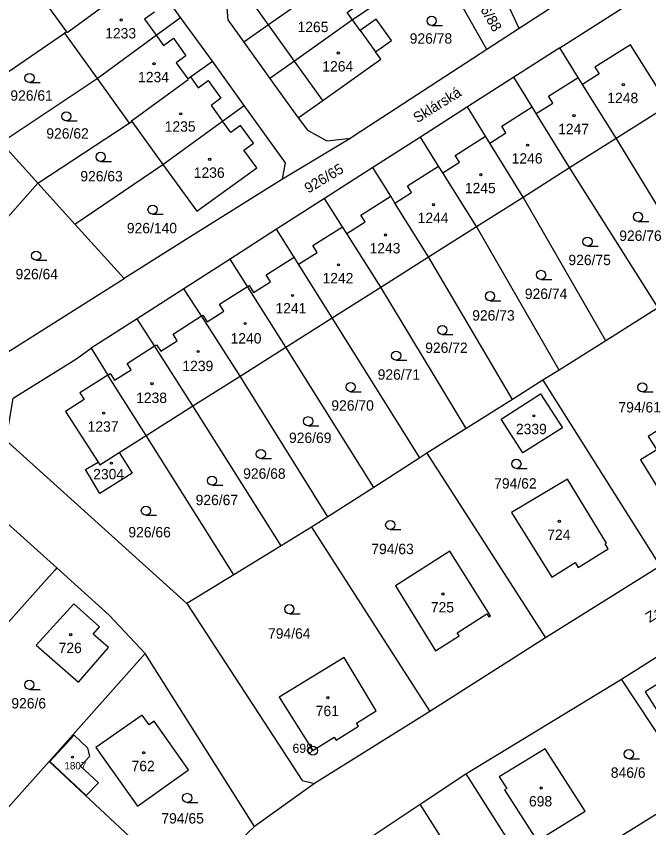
# Model space of a CAD drawing. Extents: x -680203 to -673936, y -1102717 to -1093650.
# Drawn here: x -679209.6 to -679106, y -1097911.3 to -1097778.4 of the extents above; entities that cross this region are included whole.
import ezdxf

# ---------------------------------------------------------------- set-up
doc = ezdxf.new("R2010")
doc.units = 0
for name, color, linetype in [('SOxx02xx_Koleje_param další_Popis10', 7, 'Continuous'), ('SOxx02xx_Staničení_Popis10', 7, 'Continuous'), ('SOxxxxxx_Koleje_hlavní_body_Popis10', 7, 'Continuous'), ('SOxxxxxx_Koleje_param další_Popis10', 7, 'Continuous'), ('SOxxxxxx_Osa_bod_P', 7, 'Continuous'), ('SOxxxxxx_Staničení_Popis10', 7, 'Continuous'), ('x_prac', 7, 'Continuous')]:
    doc.layers.add(name, color=color, linetype=linetype)

msp = doc.modelspace()

# ---------------------------------------------------------------- linework, layer by layer
at = {"layer": 'SOxx02xx_Koleje_param další_Popis10'}
for radius in [0.75, 0.03]:
    msp.add_circle((-679160.97, -1097898.67), radius, dxfattribs=at)
at = {"layer": 'SOxxxxxx_Koleje_hlavní_body_Popis10'}
for p, q in [((-679141.5, -1097779.94), (-679139.75, -1097779.94)), ((-679207.39, -1097789.29), (-679205.64, -1097789.29)), ((-679201.35, -1097795.58), (-679199.6, -1097795.58)), ((-679195.73, -1097802.2), (-679193.98, -1097802.2)), ((-679187.23, -1097810.84), (-679185.48, -1097810.84)), ((-679107.71, -1097812.03), (-679105.96, -1097812.03)), ((-679115.99, -1097816.08), (-679114.24, -1097816.08)), ((-679206.29, -1097818.38), (-679204.54, -1097818.38)), ((-679123.59, -1097821.53), (-679121.84, -1097821.53)), ((-679131.95, -1097825.02), (-679130.2, -1097825.02)), ((-679139.77, -1097830.56), (-679138.02, -1097830.56)), ((-679147.33, -1097834.75), (-679145.58, -1097834.75)), ((-679154.79, -1097839.9), (-679153.04, -1097839.9)), ((-679107, -1097839.95), (-679105.25, -1097839.95)), ((-679161.75, -1097845.49), (-679160, -1097845.49)), ((-679169.5, -1097850.86), (-679167.75, -1097850.86)), ((-679127.63, -1097852.47), (-679125.88, -1097852.47)), ((-679177.48, -1097855.22), (-679175.73, -1097855.22)), ((-679188.32, -1097860.13), (-679186.57, -1097860.13)), ((-679148.3, -1097862.48), (-679146.55, -1097862.48)), ((-679164.82, -1097876.26), (-679163.07, -1097876.26)), ((-679207.41, -1097888.64), (-679205.66, -1097888.64)), ((-679109.22, -1097900), (-679107.47, -1097900)), ((-679181.56, -1097907.16), (-679179.81, -1097907.16))]:
    msp.add_line(p, q, dxfattribs=at)
for centre in [(-679141.5, -1097779.19), (-679207.39, -1097788.54), (-679201.35, -1097794.83), (-679195.73, -1097801.45), (-679187.23, -1097810.09), (-679107.71, -1097811.28), (-679115.99, -1097815.33), (-679206.29, -1097817.63), (-679123.59, -1097820.78), (-679131.95, -1097824.27), (-679139.77, -1097829.81), (-679147.33, -1097834), (-679154.79, -1097839.15), (-679107, -1097839.2), (-679161.75, -1097844.74), (-679169.5, -1097850.11), (-679127.63, -1097851.72), (-679177.48, -1097854.47), (-679188.32, -1097859.38), (-679148.3, -1097861.73), (-679164.82, -1097875.51), (-679207.41, -1097887.89), (-679109.22, -1097899.25), (-679181.56, -1097906.41)]:
    msp.add_circle(centre, 0.75, dxfattribs=at)
at = {"layer": 'SOxxxxxx_Koleje_param další_Popis10'}
for centre in [(-679192.37, -1097779.05), (-679156.81, -1097784.45), (-679186.99, -1097786.21), (-679110.12, -1097789.63), (-679182.62, -1097794.41), (-679118.19, -1097794.71), (-679125.8, -1097799.54), (-679177.87, -1097801.86), (-679133.47, -1097804.38), (-679141.2, -1097809.28), (-679149.08, -1097814.25), (-679156.78, -1097819.13), (-679164.31, -1097824.16), (-679172.07, -1097828.74), (-679179.75, -1097833.32), (-679187.32, -1097838.58), (-679195.25, -1097843.43), (-679124.79, -1097843.85), (-679193.97, -1097851.61), (-679120.6, -1097861.14), (-679139.67, -1097873.03), (-679200.63, -1097879.68), (-679158.52, -1097889.99), (-679200.34, -1097899.75), (-679188.69, -1097899.02), (-679123.58, -1097904.79)]:
    msp.add_circle(centre, 0.175, dxfattribs=at)
at = {"layer": 'SOxxxxxx_Staničení_Popis10'}
for p, q in [((-679168.22, -1097779.84), (-679172.82, -1097773.44)), ((-679186.89, -1097777.74), (-679188.56, -1097778.93)), ((-679188.56, -1097778.93), (-679186.65, -1097781.55)), ((-679163.97, -1097785.76), (-679168.22, -1097779.84)), ((-679186.65, -1097781.55), (-679185.44, -1097783.21)), ((-679153.21, -1097780.77), (-679150.7, -1097784.26)), ((-679185.44, -1097783.21), (-679183.8, -1097782.04)), ((-679183.8, -1097782.04), (-679181.77, -1097784.91)), ((-679181.77, -1097784.91), (-679183.37, -1097786.05)), ((-679183.37, -1097786.05), (-679181.47, -1097788.66)), ((-679159.34, -1097792.2), (-679163.97, -1097785.76)), ((-679181.04, -1097788.35), (-679179.74, -1097790.14)), ((-679179.74, -1097790.14), (-679178.12, -1097788.96)), ((-679178.12, -1097788.96), (-679176.02, -1097791.85)), ((-679122.38, -1097791.52), (-679117.52, -1097788.45)), ((-679176.02, -1097791.85), (-679177.64, -1097793.02)), ((-679121.66, -1097792.66), (-679122.38, -1097791.52)), ((-679177.64, -1097793.02), (-679175.76, -1097795.6)), ((-679130.04, -1097796.42), (-679125.07, -1097793.28)), ((-679124.37, -1097794.38), (-679121.66, -1097792.66)), ((-679131.98, -1097799.19), (-679129.34, -1097797.52)), ((-679129.34, -1097797.52), (-679130.04, -1097796.42)), ((-679137.68, -1097801.23), (-679132.68, -1097798.07)), ((-679136.97, -1097802.34), (-679137.68, -1097801.23)), ((-679139.69, -1097804.06), (-679136.97, -1097802.34)), ((-679145.49, -1097806.19), (-679140.38, -1097802.96)), ((-679144.79, -1097807.29), (-679145.49, -1097806.19)), ((-679153.13, -1097811), (-679148.22, -1097807.89)), ((-679147.52, -1097809.01), (-679144.79, -1097807.29)), ((-679155.42, -1097814.01), (-679152.43, -1097812.11)), ((-679152.43, -1097812.11), (-679153.13, -1097811)), ((-679160.99, -1097815.99), (-679156.12, -1097812.91)), ((-679160.29, -1097817.09), (-679160.99, -1097815.99)), ((-679163.33, -1097819.01), (-679160.29, -1097817.09)), ((-679168.62, -1097820.79), (-679164.04, -1097817.89)), ((-679167.92, -1097821.91), (-679168.62, -1097820.79)), ((-679176.25, -1097825.59), (-679171.67, -1097822.69)), ((-679171.67, -1097822.69), (-679171.39, -1097822.51)), ((-679171.39, -1097822.51), (-679170.67, -1097823.65)), ((-679170.67, -1097823.65), (-679167.92, -1097821.91)), ((-679178.28, -1097828.46), (-679175.54, -1097826.72)), ((-679175.54, -1097826.72), (-679176.25, -1097825.59)), ((-679183.88, -1097830.46), (-679179.22, -1097827.51)), ((-679179.22, -1097827.51), (-679178.98, -1097827.36)), ((-679178.98, -1097827.36), (-679178.28, -1097828.46)), ((-679183.19, -1097831.56), (-679183.88, -1097830.46)), ((-679185.9, -1097833.27), (-679183.19, -1097831.56)), ((-679191.39, -1097835.27), (-679186.9, -1097832.42)), ((-679186.9, -1097832.42), (-679186.57, -1097832.22)), ((-679186.57, -1097832.22), (-679185.9, -1097833.27)), ((-679190.72, -1097836.32), (-679191.39, -1097835.27)), ((-679194.55, -1097837.18), (-679194.15, -1097836.92)), ((-679194.15, -1097836.92), (-679193.44, -1097838.04)), ((-679193.44, -1097838.04), (-679190.72, -1097836.32))]:
    msp.add_line(p, q, dxfattribs=at)
at = {"layer": 'x_prac'}
for p, q in [((-679140.59, -1097769.68), (-679154.46, -1097779.04)), ((-679182.63, -1097778.61), (-679187.59, -1097771.73)), ((-679206.43, -1097773.91), (-679201.32, -1097780.97)), ((-679177.42, -1097785.81), (-679182.63, -1097778.61)), ((-679218.09, -1097792.48), (-679201.67, -1097781.22)), ((-679201.32, -1097780.97), (-679201.67, -1097781.22)), ((-679201.67, -1097781.22), (-679196.32, -1097788.63)), ((-679127.17, -1097780.42), (-679132.45, -1097783.86)), ((-679172.27, -1097782.69), (-679168.01, -1097788.61)), ((-679120.54, -1097783.61), (-679128.06, -1097788.43)), ((-679172.22, -1097793.04), (-679177.42, -1097785.81)), ((-679212.05, -1097799.13), (-679196.32, -1097788.63)), ((-679196.32, -1097788.63), (-679191.04, -1097795.93)), ((-679128.06, -1097788.43), (-679135.63, -1097793.28)), ((-679111.3, -1097798.4), (-679116.8, -1097789.59)), ((-679175.76, -1097795.6), (-679172.22, -1097793.04)), ((-679135.63, -1097793.28), (-679143.34, -1097798.22)), ((-679206.03, -1097805.76), (-679191.04, -1097795.93)), ((-679191.04, -1097795.93), (-679190.63, -1097795.64)), ((-679190.63, -1097795.64), (-679185.55, -1097802.68)), ((-679185.55, -1097802.68), (-679175.76, -1097795.6)), ((-679154.76, -1097798.4), (-679165.95, -1097805.12)), ((-679143.34, -1097798.22), (-679151.13, -1097803.21)), ((-679118.92, -1097803.22), (-679111.3, -1097798.4)), ((-679097.14, -1097821.62), (-679111.3, -1097798.4)), ((-679206.03, -1097805.76), (-679212.05, -1097799.13)), ((-679199.95, -1097812.46), (-679185.55, -1097802.68)), ((-679151.13, -1097803.21), (-679159.05, -1097808.29)), ((-679126.54, -1097808.03), (-679118.92, -1097803.22)), ((-679104.39, -1097826.18), (-679118.92, -1097803.22)), ((-679219.28, -1097820.59), (-679206.03, -1097805.76)), ((-679206.03, -1097805.76), (-679199.95, -1097812.46)), ((-679134.18, -1097812.86), (-679126.54, -1097808.03)), ((-679113, -1097831.59), (-679126.54, -1097808.03)), ((-679159.05, -1097808.29), (-679166.91, -1097813.32)), ((-679191.86, -1097821.37), (-679199.95, -1097812.46)), ((-679166.91, -1097813.32), (-679174.51, -1097818.19)), ((-679142.02, -1097817.82), (-679134.18, -1097812.86)), ((-679120.62, -1097836.37), (-679134.18, -1097812.86)), ((-679174.51, -1097818.19), (-679182.08, -1097823.04)), ((-679149.85, -1097822.77), (-679142.02, -1097817.82)), ((-679128.28, -1097841.19), (-679142.02, -1097817.82)), ((-679157.79, -1097827.79), (-679149.85, -1097822.77)), ((-679135.85, -1097845.94), (-679149.85, -1097822.77)), ((-679182.08, -1097823.04), (-679189.74, -1097827.95)), ((-679189.74, -1097827.95), (-679197.31, -1097832.8)), ((-679165.4, -1097832.6), (-679157.79, -1097827.79)), ((-679143.47, -1097850.74), (-679157.79, -1097827.79)), ((-679113, -1097831.59), (-679120.62, -1097836.37)), ((-679197.31, -1097832.8), (-679194.55, -1097837.18)), ((-679172.9, -1097837.34), (-679165.4, -1097832.6)), ((-679150.99, -1097855.57), (-679165.4, -1097832.6)), ((-679188.3, -1097847.07), (-679194.55, -1097837.18)), ((-679180.65, -1097842.23), (-679172.9, -1097837.34)), ((-679158.52, -1097860.39), (-679172.9, -1097837.34)), ((-679120.62, -1097836.37), (-679123.28, -1097838.04)), ((-679123.28, -1097838.04), (-679128.28, -1097841.19)), ((-679123.28, -1097838.04), (-679104.07, -1097868.49)), ((-679128.28, -1097841.19), (-679135.85, -1097845.94)), ((-679188.3, -1097847.07), (-679180.65, -1097842.23)), ((-679166.18, -1097865.15), (-679180.65, -1097842.23)), ((-679135.85, -1097845.94), (-679142.29, -1097849.99)), ((-679181.63, -1097874.59), (-679211.79, -1097847.33)), ((-679192.72, -1097849.87), (-679188.3, -1097847.07)), ((-679173.9, -1097869.87), (-679188.3, -1097847.07)), ((-679143.47, -1097850.74), (-679150.99, -1097855.57)), ((-679142.29, -1097849.99), (-679143.47, -1097850.74)), ((-679142.29, -1097849.99), (-679122.86, -1097880.21)), ((-679217.61, -1097855.57), (-679202.91, -1097868.76)), ((-679150.99, -1097855.57), (-679158.52, -1097860.39)), ((-679158.52, -1097860.39), (-679161.17, -1097862.09)), ((-679161.17, -1097862.09), (-679166.18, -1097865.15)), ((-679161.17, -1097862.09), (-679141.8, -1097892.28)), ((-679166.18, -1097865.15), (-679173.9, -1097869.87)), ((-679104.07, -1097868.49), (-679122.86, -1097880.21)), ((-679173.9, -1097869.87), (-679181.63, -1097874.59)), ((-679110.44, -1097886.95), (-679097.68, -1097878.93)), ((-679122.86, -1097880.21), (-679141.8, -1097892.28)), ((-679188.43, -1097882.77), (-679204.17, -1097900.45)), ((-679170.55, -1097911.09), (-679188.43, -1097882.77)), ((-679135.92, -1097902.45), (-679110.44, -1097886.95)), ((-679098.44, -1097905.12), (-679110.44, -1097886.95)), ((-679141.8, -1097892.28), (-679160.72, -1097904.03)), ((-679204.17, -1097900.45), (-679211.82, -1097909.04)), ((-679204.17, -1097900.45), (-679181.52, -1097921.54)), ((-679143.39, -1097907.44), (-679135.92, -1097902.45)), ((-679135.92, -1097902.45), (-679124.09, -1097921.08)), ((-679160.72, -1097904.03), (-679170.55, -1097911.09)), ((-679124.09, -1097921.08), (-679098.44, -1097905.12)), ((-679161.71, -1097919.62), (-679143.39, -1097907.44)), ((-679127.29, -1097932.92), (-679143.39, -1097907.44)), ((-679170.55, -1097911.09), (-679181.52, -1097921.54))]:
    msp.add_line(p, q, dxfattribs=at)
for points in [[(-679105.77, -1097762.92), (-679107.83, -1097767.64), (-679123.65, -1097778.13), (-679127.17, -1097780.42)], [(-679127.17, -1097780.42), (-679132.44, -1097769.14), (-679127.18, -1097765.51)], [(-679201.32, -1097780.97), (-679201.22, -1097781.11), (-679191.96, -1097774.26), (-679191.86, -1097774.4), (-679191.47, -1097774.11), (-679187.59, -1097771.73)], [(-679158.7, -1097773.13), (-679168.22, -1097779.84), (-679172.27, -1097782.69)], [(-679154.46, -1097779.04), (-679155.33, -1097777.82), (-679152.73, -1097775.95), (-679155.24, -1097772.45), (-679157.84, -1097774.32), (-679158.7, -1097773.13)], [(-679120.54, -1097783.61), (-679104.92, -1097773.6), (-679101.29, -1097774.74)], [(-679175.22, -1097775.17), (-679174.9, -1097779.04), (-679172.27, -1097782.69)], [(-679132.45, -1097783.86), (-679136.81, -1097776.28), (-679137.44, -1097775.17)], [(-679196.32, -1097788.63), (-679186.65, -1097781.55), (-679182.63, -1097778.61)], [(-679163.36, -1097795.04), (-679159.34, -1097792.2), (-679149.83, -1097785.48), (-679150.7, -1097784.26), (-679148.1, -1097782.39), (-679150.61, -1097778.9), (-679153.21, -1097780.77), (-679154.46, -1097779.04)], [(-679154.46, -1097779.04), (-679163.97, -1097785.76), (-679168.01, -1097788.61)], [(-679132.45, -1097783.86), (-679154.18, -1097798.03), (-679154.76, -1097798.4)], [(-679116.8, -1097789.59), (-679117.52, -1097788.45), (-679120.54, -1097783.61)], [(-679111.3, -1097798.4), (-679102.74, -1097792.99), (-679108.95, -1097783.09), (-679114.77, -1097786.77), (-679114.07, -1097787.87), (-679116.8, -1097789.59)], [(-679190.63, -1097795.64), (-679190.7, -1097795.54), (-679181.39, -1097788.78), (-679181.47, -1097788.66), (-679181.04, -1097788.35), (-679177.42, -1097785.81)], [(-679168.01, -1097788.61), (-679167.35, -1097789.53), (-679163.36, -1097795.04)], [(-679118.92, -1097803.22), (-679124.37, -1097794.38), (-679125.07, -1097793.28), (-679128.06, -1097788.43)], [(-679165.95, -1097805.12), (-679165.43, -1097802.44), (-679172.22, -1097793.04)], [(-679126.54, -1097808.03), (-679131.98, -1097799.19), (-679132.68, -1097798.07), (-679135.63, -1097793.28)], [(-679185.55, -1097802.68), (-679180, -1097810.35), (-679170.17, -1097803.27), (-679172.29, -1097800.37), (-679170.72, -1097799.22), (-679172.85, -1097796.3), (-679174.41, -1097797.45), (-679175.76, -1097795.6)], [(-679163.36, -1097795.04), (-679161.87, -1097797.08), (-679158.69, -1097798.85), (-679154.76, -1097798.4)], [(-679134.18, -1097812.86), (-679139.69, -1097804.06), (-679140.38, -1097802.96), (-679143.34, -1097798.22)], [(-679142.02, -1097817.82), (-679147.52, -1097809.01), (-679148.22, -1097807.89), (-679151.13, -1097803.21)], [(-679165.95, -1097805.12), (-679181.84, -1097815.06), (-679191.86, -1097821.37)], [(-679149.85, -1097822.77), (-679155.42, -1097814.01), (-679156.12, -1097812.91), (-679159.05, -1097808.29)], [(-679157.79, -1097827.79), (-679163.33, -1097819.01), (-679164.04, -1097817.89), (-679166.91, -1097813.32)], [(-679165.4, -1097832.6), (-679171.67, -1097822.69), (-679174.51, -1097818.19)], [(-679221.83, -1097838.26), (-679218.85, -1097838.36), (-679214.73, -1097835.76), (-679191.86, -1097821.37)], [(-679172.9, -1097837.34), (-679179.22, -1097827.51), (-679182.08, -1097823.04)], [(-679104.39, -1097826.18), (-679105.37, -1097826.8), (-679113, -1097831.59)], [(-679180.65, -1097842.23), (-679186.9, -1097832.42), (-679189.74, -1097827.95)], [(-679211.79, -1097847.33), (-679210.76, -1097845.25), (-679210.07, -1097840.98), (-679199.82, -1097834.58), (-679197.31, -1097832.8)], [(-679194.55, -1097837.18), (-679199.15, -1097840.09), (-679198.44, -1097841.2), (-679201.47, -1097843.12), (-679196.16, -1097851.45)], [(-679130.11, -1097844.38), (-679123.67, -1097840.26), (-679120.11, -1097845.82), (-679126.56, -1097849.93), (-679130.11, -1097844.38)], [(-679093.93, -1097852.83), (-679098.77, -1097845.27), (-679099.97, -1097843.4), (-679106.07, -1097847.25), (-679104.65, -1097849.43), (-679107.32, -1097851.08), (-679102.81, -1097858.3), (-679100.9, -1097861.34), (-679094.06, -1097857.16), (-679095.97, -1097854.08), (-679093.93, -1097852.83)], [(-679192.72, -1097849.87), (-679190.59, -1097853.23), (-679195.89, -1097856.59), (-679198.2, -1097852.66), (-679196.16, -1097851.45)], [(-679196.16, -1097851.45), (-679195.89, -1097851.87), (-679192.72, -1097849.87)], [(-679112.86, -1097864.68), (-679119.28, -1097854.21), (-679128.42, -1097859.69), (-679121.82, -1097870.26), (-679117.99, -1097867.88), (-679117.49, -1097868.68), (-679112.61, -1097865.64), (-679113.11, -1097864.84), (-679112.86, -1097864.68)], [(-679137, -1097879.87), (-679137.32, -1097879.37), (-679132.46, -1097876.28), (-679132.14, -1097876.77), (-679131.85, -1097876.59), (-679138.53, -1097865.99), (-679147.46, -1097871.7), (-679140.87, -1097882.32), (-679137, -1097879.87)], [(-679202.91, -1097868.76), (-679203.24, -1097869.12), (-679226.85, -1097895.47)], [(-679202.91, -1097868.76), (-679194.32, -1097876.47), (-679188.43, -1097882.77)], [(-679194.45, -1097881.8), (-679196.94, -1097879.58), (-679195.9, -1097878.41), (-679200.13, -1097874.66), (-679206.27, -1097881.39), (-679199.38, -1097887.46), (-679194.45, -1097881.8)], [(-679181.63, -1097874.59), (-679162.72, -1097903.55), (-679160.72, -1097904.03)], [(-679166.49, -1097889.92), (-679160.97, -1097898.67), (-679157.47, -1097896.48), (-679157.16, -1097896.98), (-679153.51, -1097894.69), (-679153.82, -1097894.19), (-679150.58, -1097892.17), (-679155.82, -1097883.42), (-679166.49, -1097889.92)], [(-679106.52, -1097889.07), (-679099.8, -1097899.58), (-679091.33, -1097894.33), (-679097.94, -1097883.68), (-679106.52, -1097889.07)], [(-679187.81, -1097894.46), (-679188.94, -1097892.84), (-679196.52, -1097898.15), (-679189.68, -1097907.76), (-679181.32, -1097901.8), (-679186.97, -1097893.86), (-679187.81, -1097894.46)], [(-679199.04, -1097901.19), (-679196.11, -1097903.92), (-679198.09, -1097906.04), (-679204.07, -1097900.46), (-679200.05, -1097896.13), (-679197.86, -1097898.19), (-679197.57, -1097899.62), (-679199.04, -1097901.19)], [(-679129.56, -1097905.1), (-679124.23, -1097913.42), (-679116.39, -1097908.57), (-679122.9, -1097898.36), (-679130.43, -1097902.96), (-679129.2, -1097904.87), (-679129.56, -1097905.1)]]:
    msp.add_lwpolyline(points, dxfattribs=at)

# ---------------------------------------------------------------- texts
at = {"layer": 'SOxx02xx_Koleje_param další_Popis10'}
msp.add_text('698', height=1.5, dxfattribs=at).set_placement((-679164.31, -1097899.04))
at = {"layer": 'SOxx02xx_Staničení_Popis10'}
for s, p in [('Sklárská', (-679143.87, -1097795.97)), ('Zahrádecká', (-679105.81, -1097877.78))]:
    msp.add_text(s, height=1.7, rotation=32, dxfattribs=at).set_placement(p)
at = {"layer": 'SOxxxxxx_Osa_bod_P'}
for s, rotation, p in [('926/88', 300, (-679134.87, -1097775.12)), ('926/65', 31, (-679161.71, -1097807.48))]:
    msp.add_text(s, height=1.7, rotation=rotation, dxfattribs=at).set_placement(p)
for s, height, p in [('1265', 1.7, (-679163.48, -1097781.03)), ('1233', 1.7, (-679194.98, -1097782.07)), ('926/78', 1.7, (-679145.11, -1097782.92)), ('1264', 1.7, (-679159.42, -1097787.48)), ('1234', 1.7, (-679189.6, -1097789.24)), ('926/61', 1.7, (-679210.52, -1097792.26)), ('1248', 1.7, (-679112.74, -1097792.66)), ('1235', 1.7, (-679185.24, -1097797.33)), ('1247', 1.7, (-679120.8, -1097797.74)), ('926/62', 1.7, (-679204.63, -1097798.47)), ('1246', 1.7, (-679128.41, -1097802.56)), ('926/63', 1.7, (-679199.06, -1097805.47)), ('1236', 1.7, (-679180.48, -1097804.89)), ('1245', 1.7, (-679136.08, -1097807.41)), ('1244', 1.7, (-679143.81, -1097812.3)), ('926/140', 1.7, (-679191.44, -1097813.97)), ('926/76', 1.7, (-679110.79, -1097815.21)), ('1243', 1.7, (-679151.69, -1097817.27)), ('926/75', 1.7, (-679119.11, -1097819.18)), ('926/64', 1.7, (-679209.67, -1097821.5)), ('1242', 1.7, (-679159.39, -1097822.16)), ('926/74', 1.7, (-679126.25, -1097824.72)), ('1241', 1.7, (-679167.1, -1097827.1)), ('926/73', 1.7, (-679134.87, -1097828.26)), ('1240', 1.7, (-679174.45, -1097832.02)), ('926/72', 1.7, (-679142.57, -1097833.56)), ('1239', 1.7, (-679182.34, -1097836.53)), ('926/71', 1.7, (-679150.36, -1097837.94)), ('1238', 1.7, (-679189.92, -1097841.75)), ('926/70', 1.7, (-679157.94, -1097843.01)), ('794/61', 1.7, (-679110.92, -1097843.3)), ('1237', 1.7, (-679197.86, -1097846.46)), ('2339', 1.7, (-679127.71, -1097846.86)), ('926/69', 1.7, (-679164.88, -1097848.3)), ('2304', 1.7, (-679196.95, -1097854.25)), ('926/68', 1.7, (-679172.39, -1097854.16)), ('794/62', 1.7, (-679131.28, -1097855.77)), ('926/67', 1.7, (-679180.17, -1097858.48)), ('926/66', 1.7, (-679191.19, -1097863.76)), ('724', 1.7, (-679122.58, -1097864.17)), ('794/63', 1.7, (-679151.4, -1097866.5)), ('725', 1.7, (-679141.65, -1097876.05)), ('794/64', 1.7, (-679168.31, -1097880.34)), ('726', 1.7, (-679202.61, -1097882.71)), ('926/6', 1.7, (-679210.36, -1097891.77)), ('761', 1.7, (-679160.5, -1097893.02)), ('1807', 1.2, (-679201.66, -1097901.75)), ('762', 1.7, (-679190.67, -1097902.04)), ('846/6', 1.7, (-679112.17, -1097903.12)), ('698', 1.7, (-679125.57, -1097907.81)), ('794/65', 1.7, (-679185.78, -1097910.61))]:
    msp.add_text(s, height=height, dxfattribs=at).set_placement(p)

doc.saveas('drawing.dxf')
